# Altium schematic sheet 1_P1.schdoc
size 431 x 309 mm; Symbol: Sheet-Symbol_A1; Device: Sheet-Symbol_A1; Company: MadNick93; Drawed: Niccolo&apos; Ferrari; Reviewed: Niccolo&apos; Ferrari; Version: V4.0; Page Size: A1; @Project Name: Compact_LED_Driver_PWM_Single_ATtiny1616_Double; @Page Count: 1; @Update Date: 2024-02-11; @Create Date: 2024-02-08; @Schematic Name: schematic1; Part Number: NF-0001; @Page No: 1; @Page Name: P1; @Board Name: Board1; @Create Time: 16:56:16; @Update Time: 14:38:09
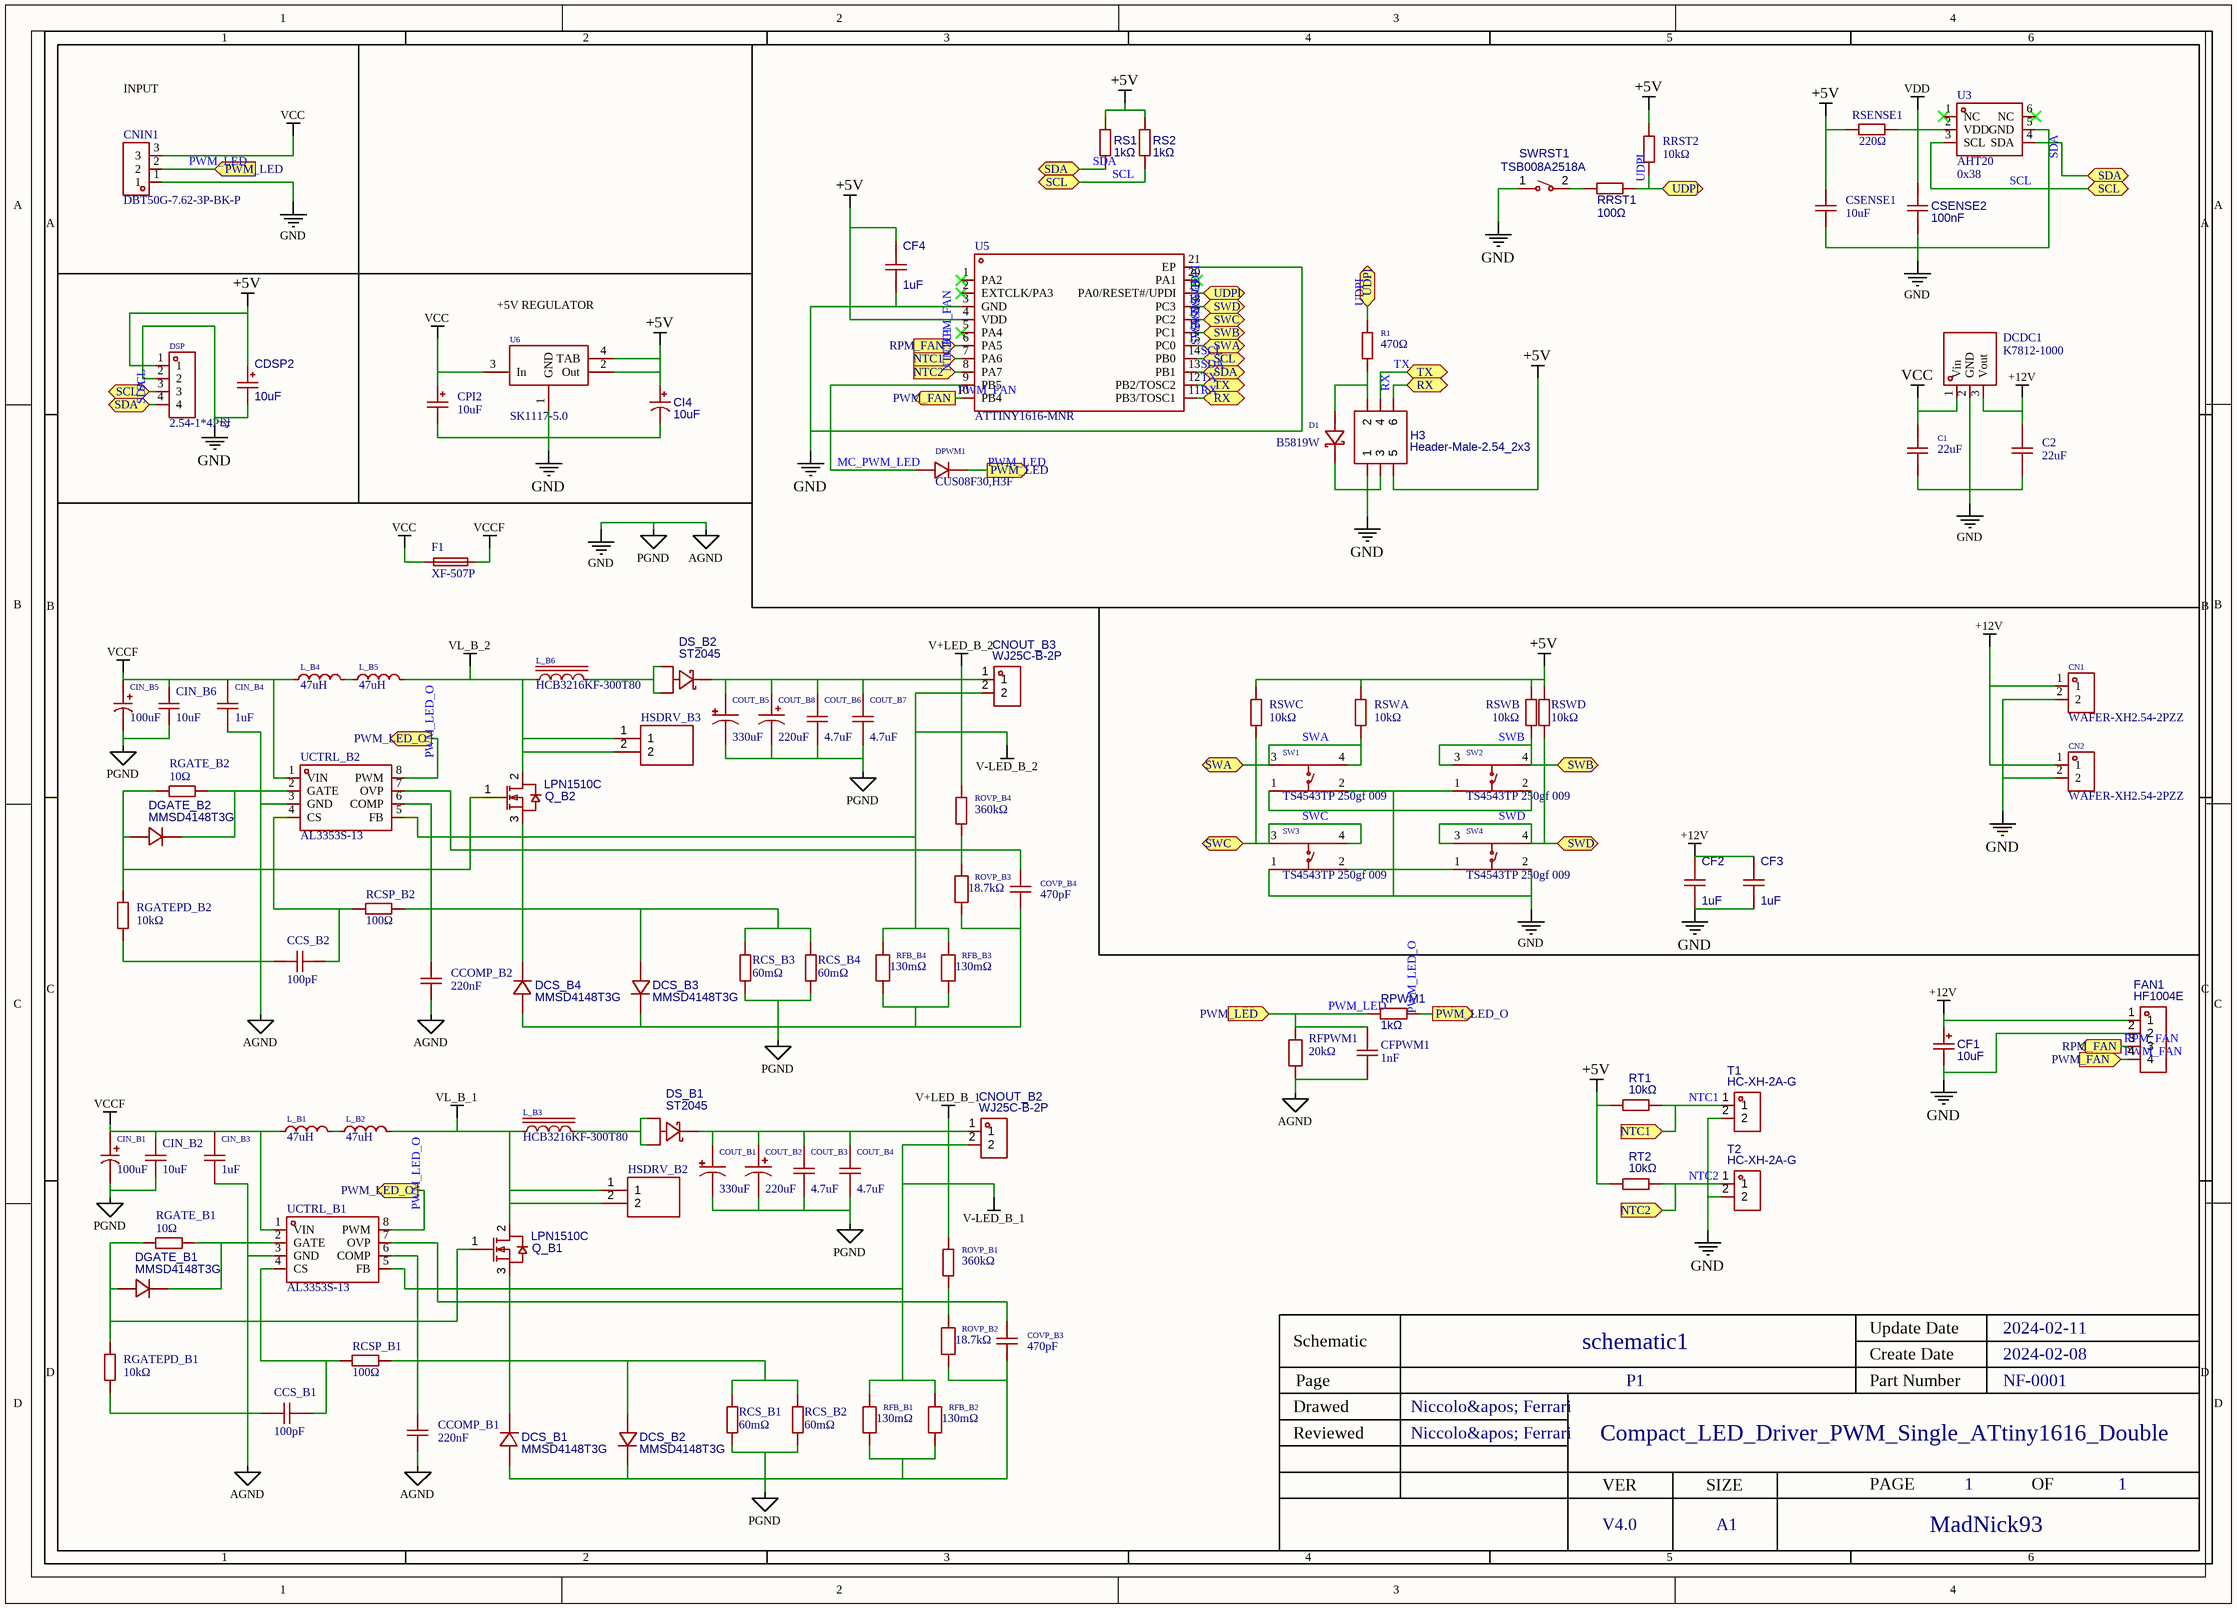
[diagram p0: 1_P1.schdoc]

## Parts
C1  22uF  [C0805]  (value not drawn)
C2  22uF  [C0805]  (value not drawn)
CCOMP_B1  220nF  [C0402]  (value not drawn)
CCOMP_B2  220nF  [C0402]  (value not drawn)
CCS_B1  100pF  [C0402]  (value not drawn)
CCS_B2  100pF  [C0402]  (value not drawn)
CDSP2  10uF  [CAP-SMD_L3.2-W1.6-R-RD]  (value not drawn)
CF1  10uF  [CAP-SMD_L3.5-W2.8]  (value not drawn)
CF2  1uF  [0402]  (value not drawn)
CF3  1uF  [0402]  (value not drawn)
CF4  1uF  [0402]  (value not drawn)
CFPWM1  1nF  [C0603]  (value not drawn)
CI4  10uF  [CAP-SMD_L3.2-W1.6]  (value not drawn)
CIN_B1  100uF  [CAP-TH_BD10.0-P5.00-D0.6-FD-A]  (value not drawn)
CIN_B2  10uF  [C0805]  (value not drawn)
CIN_B3  1uF  [C0402]  (value not drawn)
CIN_B4  1uF  [C0402]  (value not drawn)
CIN_B5  100uF  [CAP-TH_BD10.0-P5.00-D0.6-FD-A]  (value not drawn)
CIN_B6  10uF  [C0805]  (value not drawn)
CN1  WAFER-XH2.54-2PZZ  [CONN-TH_XH2.54-2P]  (value not drawn)
CN2  WAFER-XH2.54-2PZZ  [CONN-TH_XH2.54-2P]  (value not drawn)
CNIN1  DBT50G-7.62-3P-BK-P  [CONN-TH_3P-P7.62_L15.2-W24.4-EX4.2]  (value not drawn)
CNOUT_B2  WJ25C-B-2P  [CONN-TH_2P-P7.62_WJ25C-B-7.62-2P]  (value not drawn)
CNOUT_B3  WJ25C-B-2P  [CONN-TH_2P-P7.62_WJ25C-B-7.62-2P]  (value not drawn)
COUT_B1  330uF  [CAP-TH_BD10.0-P5.00-D1.0-FD]  (value not drawn)
COUT_B2  220uF  [CAP-TH_BD10.0-P5.00-D0.6-FD-A]  (value not drawn)
COUT_B3  4.7uF  [C1210]  (value not drawn)
COUT_B4  4.7uF  [C1210]  (value not drawn)
COUT_B5  330uF  [CAP-TH_BD10.0-P5.00-D1.0-FD]  (value not drawn)
COUT_B6  4.7uF  [C1210]  (value not drawn)
COUT_B7  4.7uF  [C1210]  (value not drawn)
COUT_B8  220uF  [CAP-TH_BD10.0-P5.00-D0.6-FD-A]  (value not drawn)
COVP_B3  470pF  [C0402]  (value not drawn)
COVP_B4  470pF  [C0402]  (value not drawn)
CPI2  10uF  [CASE-C_6032]  (value not drawn)
CSENSE1  10uF  [C0402]  (value not drawn)
CSENSE2  100nF  [C0402]  (value not drawn)
D1  B5819W  [SOD-123F_L2.7-W1.6-LS3.8-RD-1]  (value not drawn)
DCDC1  K7812-1000  [PWRM-TH_K78XX-1000]  (value not drawn)
DCS_B1  MMSD4148T3G  [SOD-123FL_L2.6-W1.6-LS3.4-RD]  (value not drawn)
DCS_B2  MMSD4148T3G  [SOD-123FL_L2.6-W1.6-LS3.4-RD]  (value not drawn)
DCS_B3  MMSD4148T3G  [SOD-123FL_L2.6-W1.6-LS3.4-RD]  (value not drawn)
DCS_B4  MMSD4148T3G  [SOD-123FL_L2.6-W1.6-LS3.4-RD]  (value not drawn)
DGATE_B1  MMSD4148T3G  [SOD-123FL_L2.6-W1.6-LS3.4-RD]  (value not drawn)
DGATE_B2  MMSD4148T3G  [SOD-123FL_L2.6-W1.6-LS3.4-RD]  (value not drawn)
DPWM1  CUS08F30,H3F  [SOD-323F_L2.0-W1.6-LS2.5-RD]  (value not drawn)
DS_B1  ST2045  [TO-277_3P-L5.4-W4.0-LS6.5-BR]  (value not drawn)
DS_B2  ST2045  [TO-277_3P-L5.4-W4.0-LS6.5-BR]  (value not drawn)
DSP  2.54-1*4P母  [HDR-TH_4P-P2.54-V-F]  (value not drawn)
F1  XF-507P  [CONN-TH_XF-507P]  (value not drawn)
FAN1  HF1004E  [CONN-TH_4P-P2.54_HF1004E]  (value not drawn)
H3  Header-Male-2.54_2x3  [HDR-TH_6P-P2.54-V-M-R2-C3-S2.54-1]  (value not drawn)
HSDRV_B2  XSD366-094  [xsd366094]  (value not drawn)
HSDRV_B3  XSD366-094  [xsd366094]  (value not drawn)
L_B1  47uH  [IND-TH_L17.8-W17.8-P13.00-D0.6]  (value not drawn)
L_B2  47uH  [IND-TH_L17.8-W17.8-P13.00-D0.6]  (value not drawn)
L_B3  HCB3216KF-300T80  [L1206]  (value not drawn)
L_B4  47uH  [IND-TH_L17.8-W17.8-P13.00-D0.6]  (value not drawn)
L_B5  47uH  [IND-TH_L17.8-W17.8-P13.00-D0.6]  (value not drawn)
L_B6  HCB3216KF-300T80  [L1206]  (value not drawn)
Q_B1  LPN1510C  [TO-220-3_L10.0-W4.5-P2.54-L]  (value not drawn)
Q_B2  LPN1510C  [TO-220-3_L10.0-W4.5-P2.54-L]  (value not drawn)
R1  470Ω  [R0402]  (value not drawn)
RCS_B1  60mΩ  [R2512]  (value not drawn)
RCS_B2  60mΩ  [R2512]  (value not drawn)
RCS_B3  60mΩ  [R2512]  (value not drawn)
RCS_B4  60mΩ  [R2512]  (value not drawn)
RCSP_B1  100Ω  [R0402]  (value not drawn)
RCSP_B2  100Ω  [R0402]  (value not drawn)
RFB_B1  130mΩ  [RES-SMD_L6.4-W3.2-R2512]  (value not drawn)
RFB_B2  130mΩ  [RES-SMD_L6.4-W3.2-R2512]  (value not drawn)
RFB_B3  130mΩ  [RES-SMD_L6.4-W3.2-R2512]  (value not drawn)
RFB_B4  130mΩ  [RES-SMD_L6.4-W3.2-R2512]  (value not drawn)
RFPWM1  20kΩ  [R0402]  (value not drawn)
RGATE_B1  10Ω  [R0402]  (value not drawn)
RGATE_B2  10Ω  [R0402]  (value not drawn)
RGATEPD_B1  10kΩ  [R0402]  (value not drawn)
RGATEPD_B2  10kΩ  [R0402]  (value not drawn)
ROVP_B1  360kΩ  [R0402]  (value not drawn)
ROVP_B2  18.7kΩ  [R0402]  (value not drawn)
ROVP_B3  18.7kΩ  [R0402]  (value not drawn)
ROVP_B4  360kΩ  [R0402]  (value not drawn)
RPWM1  1kΩ  [R0402]  (value not drawn)
RRST1  100Ω  [R0402]  (value not drawn)
RRST2  10kΩ  [R0402]  (value not drawn)
RS1  1kΩ  [R0402]  (value not drawn)
RS2  1kΩ  [R0402]  (value not drawn)
RSENSE1  220Ω  [R0402]  (value not drawn)
RSWA  10kΩ  [R0402]  (value not drawn)
RSWB  10kΩ  [R0402]  (value not drawn)
RSWC  10kΩ  [R0402]  (value not drawn)
RSWD  10kΩ  [R0402]  (value not drawn)
RT1  10kΩ  [R0402]  (value not drawn)
RT2  10kΩ  [R0402]  (value not drawn)
SW1  TS4543TP 250gf 009  [SW-SMD_4P-L4.5-W4.5-P3.00-LS6.9]  (value not drawn)
SW2  TS4543TP 250gf 009  [SW-SMD_4P-L4.5-W4.5-P3.00-LS6.9]  (value not drawn)
SW3  TS4543TP 250gf 009  [SW-SMD_4P-L4.5-W4.5-P3.00-LS6.9]  (value not drawn)
SW4  TS4543TP 250gf 009  [SW-SMD_4P-L4.5-W4.5-P3.00-LS6.9]  (value not drawn)
SWRST1  TSB008A2518A  [SW-SMD_L6.0-W3.5-LS8.2]  (value not drawn)
T1  HC-XH-2A-G  [CONN-TH_2P-P2.50_HC-XH-2A-G]  (value not drawn)
T2  HC-XH-2A-G  [CONN-TH_2P-P2.50_HC-XH-2A-G]  (value not drawn)
U3  I2C Address: 0x38  [SENSOR-SMD_L3.0-W3.0-P1.00-BR]  (hidden comment: AHT20)
U5  ATTINY1616-MNR  [QFN-20_L3.0-W3.0-P0.40-BL-EP1.7]  (value not drawn)
U6  SK1117-5.0  [SOT-223_L6.5-W3.5-P2.30-LS7.0-BR]  (value not drawn)
UCTRL_B1  AL3353S-13  [SOIC-8_L4.9-W3.9-P1.27-LS6.0-BL]  (value not drawn)
UCTRL_B2  AL3353S-13  [SOIC-8_L4.9-W3.9-P1.27-LS6.0-BL]  (value not drawn)

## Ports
NTC1 (in), NTC2 (in), PWM_FAN (in), PWM_FAN (out), PWM_LED (in), PWM_LED (out), PWM_LED_O (out), RPM_FAN (in), RPM_FAN (out), RX (bidir), SCL (bidir), SDA (bidir), SWA (bidir), SWB (bidir), SWC (bidir), SWD (bidir), TX (bidir), UDPI (bidir)

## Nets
+5V: CDSP2.1 CF4.1 CI4.1 CSENSE1.2 DSP.1 H3.5 RRST2.2 RS1.2 RS2.2 RSENSE1.1 RSWA.2 RSWB.2 RSWC.2 RSWD.2 RT1.1 RT2.1 U5.4(VDD) U6.2(Out) U6.4(TAB)
+12V: C2.1 CF1.1 CF2.1 CF3.1 CN1.1 CN2.1 DCDC1.3(Vout) FAN1.1
AGND: C1.2 C2.2 CCOMP_B1.2 CCOMP_B2.2 CCS_B1.2 CCS_B2.2 CDSP2.2 CF1.2 CF2.2 CF3.2 CF4.2 CFPWM1.1 CI4.2 CIN_B1.2 CIN_B2.2 CIN_B3.1 CIN_B4.1 CIN_B5.2 CIN_B6.2 CN1.2 CN2.2 CNIN1.1 COUT_B1.2 COUT_B2.2 COUT_B3.1 COUT_B4.1 COUT_B5.2 COUT_B6.1 COUT_B7.1 COUT_B8.2 COVP_B3.1 COVP_B4.1 CPI2.2 CSENSE1.1 CSENSE2.1 DCDC1.2(GND) DCS_B1.2(A) DCS_B2.1(C) DCS_B3.1(C) DCS_B4.2(A) DSP.2 FAN1.2 H3.1 RCS_B1.1 RCS_B2.1 RCS_B3.1 RCS_B4.1 RFB_B1.1 RFB_B2.1 RFB_B3.1 RFB_B4.1 RFPWM1.1 RGATEPD_B1.1 RGATEPD_B2.1 ROVP_B2.1 ROVP_B3.1 SW1.1(A) SW1.2(B) SW2.1(A) SW2.2(B) SW3.1(A) SW3.2(B) SW4.1(A) SW4.2(B) SWRST1.1 T1.2 T2.2 U3.5(GND) U5.3(GND) U5.21(EP) U6.1(GND) UCTRL_B1.3(GND) UCTRL_B2.3(GND)  [also labelled GND, PGND]
V+LED_B_1: CNOUT_B2.1 COUT_B1.1 COUT_B2.1 COUT_B3.2 COUT_B4.2 DS_B1.2(K) ROVP_B1.2
V+LED_B_2: CNOUT_B3.1 COUT_B5.1 COUT_B6.2 COUT_B7.2 COUT_B8.1 DS_B2.2(K) ROVP_B4.2
V-LED_B_1: CNOUT_B2.2 RFB_B1.2 RFB_B2.2 UCTRL_B1.5(FB)
V-LED_B_2: CNOUT_B3.2 RFB_B3.2 RFB_B4.2 UCTRL_B2.5(FB)
VCC: C1.1 CNIN1.3 CPI2.1 DCDC1.1(Vin) F1.1 F1.2 U6.3(In)
VCCF: CIN_B1.1 CIN_B2.1 CIN_B3.2 CIN_B4.2 CIN_B5.1 CIN_B6.1 F1.3 F1.4 L_B1.1 L_B4.1 UCTRL_B1.1(VIN) UCTRL_B2.1(VIN)
VDD: CSENSE2.2 RSENSE1.2 U3.2(VDD)
VL_B_1: HSDRV_B2.1 HSDRV_B2.2 L_B2.2 L_B3.1 Q_B1.2(D)
VL_B_2: HSDRV_B3.1 HSDRV_B3.2 L_B5.2 L_B6.1 Q_B2.2(D)
MC_PWM_LED: DPWM1.2(A) U5.9(PB5)
NTC1: RT1.2 T1.1 U5.7(PA6) ; port NTC1
NTC2: RT2.2 T2.1 U5.8(PA7) ; port NTC2
PWM_FAN: FAN1.4 U5.10(PB4) ; port PWM_FAN
PWM_LED: CFPWM1.2 CNIN1.2 DPWM1.1(C) RFPWM1.2 RPWM1.2 ; port PWM_LED
PWM_LED_O: RPWM1.1 UCTRL_B1.8(PWM) UCTRL_B2.8(PWM) ; port PWM_LED_O
RPM_FAN: FAN1.3 U5.6(PA5) ; port RPM_FAN
RX: H3.6 U5.11(PB3/TOSC1) ; port RX
SCL: DSP.3 RS2.1 U3.3(SCL) U5.14(PB0) ; port SCL
SDA: DSP.4 RS1.1 U3.4(SDA) U5.13(PB1) ; port SDA
SWA: RSWA.1 SW1.3(C) SW1.4(D) U5.15(PC0) ; port SWA
SWB: RSWB.1 SW2.3(C) SW2.4(D) U5.16(PC1) ; port SWB
SWC: RSWC.1 SW3.3(C) SW3.4(D) U5.17(PC2) ; port SWC
SWD: RSWD.1 SW4.3(C) SW4.4(D) U5.18(PC3) ; port SWD
TX: H3.4 U5.12(PB2/TOSC2) ; port TX
UDPI: R1.2 RRST1.1 RRST2.1 U5.19(PA0/RESET#/UPDI) ; port UDPI
NetCCOMP_B1_1: CCOMP_B1.1 UCTRL_B1.6(COMP)
NetCCOMP_B2_1: CCOMP_B2.1 UCTRL_B2.6(COMP)
NetCCS_B1_1: CCS_B1.1 RCSP_B1.1 UCTRL_B1.4(CS)
NetCCS_B2_1: CCS_B2.1 RCSP_B2.1 UCTRL_B2.4(CS)
NetCOVP_B3_2: COVP_B3.2 ROVP_B1.1 ROVP_B2.2 UCTRL_B1.7(OVP)
NetCOVP_B4_2: COVP_B4.2 ROVP_B3.2 ROVP_B4.1 UCTRL_B2.7(OVP)
NetD1_1: D1.1(K) H3.3
NetD1_2: D1.2(A) H3.2 R1.1
NetDCS_B1_1: DCS_B1.1(C) DCS_B2.2(A) Q_B1.3(S) RCS_B1.2 RCS_B2.2 RCSP_B1.2
NetDCS_B3_2: DCS_B3.2(A) DCS_B4.1(C) Q_B2.3(S) RCS_B3.2 RCS_B4.2 RCSP_B2.2
NetDGATE_B1_1: DGATE_B1.1(C) RGATE_B1.2 UCTRL_B1.2(GATE)
NetDGATE_B1_2: DGATE_B1.2(A) Q_B1.1(G) RGATE_B1.1 RGATEPD_B1.2
NetDGATE_B2_1: DGATE_B2.1(C) RGATE_B2.2 UCTRL_B2.2(GATE)
NetDGATE_B2_2: DGATE_B2.2(A) Q_B2.1(G) RGATE_B2.1 RGATEPD_B2.2
NetDS_B1_1: DS_B1.1(A) DS_B1.3(A) L_B3.2
NetDS_B2_1: DS_B2.1(A) DS_B2.3(A) L_B6.2
NetL_B1_2: L_B1.2 L_B2.1
NetL_B4_2: L_B4.2 L_B5.1
NetRRST1_2: RRST1.2 SWRST1.2

Not connected (* = marked no-connect by the designer): U3 1(NC)* 6(NC)*; U5 1(PA2)* 2(EXTCLK/PA3)* 5(PA4)* 20(PA1)*

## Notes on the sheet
- INPUT
- (near U6) +5V REGULATOR

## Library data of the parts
C1 = CGA0805X5R226M350MT: Capacitance:22uF Tolerance:±20% Tolerance:±20% Voltage Rated: Temperature Coefficient:; Manufacturer: HRE(芯声); Add into BOM: yes; Tolerance: ±20%
C2 = CL21A226MAYNNNE: Capacitance: Tolerance:±20% Tolerance:±20% Voltage Rated: Temperature Coefficient:; Manufacturer: SAMSUNG(三星); Add into BOM: yes; Tolerance: ±20%
CCOMP_B1 CCOMP_B2 = CL05A224KA5NNNC: Capacitance: Tolerance:±10% Tolerance:±10% Voltage Rated: Temperature Coefficient:; Manufacturer: SAMSUNG(三星); Add into BOM: yes; Tolerance: ±10%
CCS_B1 CCS_B2 = TCC0402COG101K500AT: Capacitance: Tolerance:±10% Tolerance:±10% Voltage Rated: Temperature Coefficient:; Manufacturer: CCTC(三环); Add into BOM: yes; Tolerance: ±10%
CDSP2 = 10uF: Manufacturer: AVX; Manufacturer Part: TAJA106K010RNJ; Convert to PCB: yes
CF1 = 10uF: Manufacturer: Xiangyee; Manufacturer Part: CA45-B025K106T; Convert to PCB: yes
CF2-CF4 = 1uF: Manufacturer: SAMSUNG; Manufacturer Part: CL05A105KA5NQNC; Convert to PCB: yes
CFPWM1 = FN18X102K500PSG: Capacitance: Tolerance:±10% Tolerance:±10% Voltage Rated: Temperature Coefficient:; Manufacturer: PSA(信昌电陶); Add into BOM: yes; Tolerance: ±10%
CI4 = 10uF: Manufacturer: Xiangyee; Manufacturer Part: CA45-A016K106T; Convert to PCB: yes
CIN_B1 CIN_B5 = 1010631012R00: Capacitance: Tolerance:±20% Tolerance:±20% Rated Voltage: φD: L: Operating Temperature:-55℃~+105℃ Operating Temperature:-55℃~+105℃; Manufacturer: NJCON(永立); Add into BOM: yes; Tolerance: ±20%
CIN_B2 CIN_B6 = CL21A106KAYNNNE_C15850: Capacitance: Tolerance:±10% Tolerance:±10% Voltage Rated: Temperature Coefficient:; Manufacturer: SAMSUNG(三星); Add into BOM: yes; Tolerance: ±10%
CIN_B3 CIN_B4 = CL05A105KA5NQNC: Capacitance: Tolerance:±10% Tolerance:±10% Voltage Rated: Temperature Coefficient:; Manufacturer: SAMSUNG(三星); Add into BOM: yes; Tolerance: ±10%
CN1 CN2 = WAFER-XH2.54-2PZZ: Pins Structure:1x2P Pitch:2.54mm Mounting Style:Straight Number of Pins:2P Number of Rows:1 Number of PINs Per Row:2 Current Rating (Max):2A Operating Temperature Range:-25℃~+85℃ Operating Temperature Range:-25℃~+85℃; Manufacturer: XUNPU(讯普); Add into BOM: yes; Pins Structure: 1x2P; Pitch: 2.54mm; Number of PINs Per Row: 2; Current Rating (Max): 2A
CNIN1 = DBT50G-7.62-3P-BK-P: Barrier Type:带盖板 Pitch:7.62mm Number of PINs Per Row:3 Number of Rows:1 Mounting Style:直针 Pin Location:边脚 Current Rating (Max):20A Voltage Rating (Max):300V Wire Gauge - AWG:12~22 Wire Gauge - mm?:- Operating Temperature Range:-40℃~+105℃ Operating Tempera; Manufacturer: DIBO(地博电气); Add into BOM: yes; Barrier Type: 带盖板; Pitch: 7.62mm; Number of PINs Per Row: 3; Pin Location: 边脚; Current Rating (Max): 20A; Voltage Rating (Max): 300V; Wire Gauge - AWG: 12~22
CNOUT_B2 CNOUT_B3 = WJ25C-B-2P: Manufacturer: KANGNEX(康奈克斯电气); Manufacturer Part: WJ25C-B-7.62-2P; Convert to PCB: yes
COUT_B1 COUT_B5 = RG063M331LO10*20TA-1A1E: Capacitance: Tolerance:±20% Tolerance:±20% Rated Voltage: Lead Spacing: φD: L: Lifetime @ Temp:7000hrs@105℃; Manufacturer: BERYL(绿宝石); Add into BOM: yes; Tolerance: ±20%
COUT_B2 COUT_B8 = SPZ1JM221G15O00RAXXX: Capacitance: Tolerance:±20% Tolerance:±20% Rated Voltage: Ripple Current:2.65A@100kHz Equivalent Series Resistance(ESR):20mΩ@100kHz Type:Polymer Lead Spacing: φD: L: Lifetime @ Temp:2000hrs@105℃ Operating Temperature:-55℃~+105℃ Operating Temperature:-55℃~; Manufacturer: AISHI(艾华集团); Add into BOM: yes; Tolerance: ±20%
COUT_B3 COUT_B4 COUT_B6 COUT_B7 = FS32X475K101EGG: Capacitance: Tolerance:±10% Tolerance:±10% Voltage Rated: Temperature Coefficient:; Manufacturer: PSA(信昌电陶); Add into BOM: yes; Tolerance: ±10%
COVP_B3 COVP_B4 = 0402B471K500NT: Capacitance: Tolerance:±10% Tolerance:±10% Voltage Rated: Temperature Coefficient:; Manufacturer: FH(风华); Add into BOM: yes; Tolerance: ±10%
CPI2 = TAJC106K035RNJ: Capacitance: Tolerance:±10% Tolerance:±10% Rated Voltage: Equivalent Series Resistance(ESR):1.6Ω@100kHz Operating Temperature:-55℃~+125℃ Operating Temperature:-55℃~+125℃; Manufacturer: Kyocera AVX; Add into BOM: yes; Tolerance: ±10%
CSENSE1 = CL05A106MQ5NUNC: Capacitance: Tolerance:±20% Tolerance:±20% Voltage Rated: Temperature Coefficient:; Manufacturer: SAMSUNG(三星); Add into BOM: yes; Tolerance: ±20%
CSENSE2 = 100nF: Manufacturer: CCTC(三环); Manufacturer Part: TCC0402X7R104K160AT; Convert to PCB: yes
D1 = B5819W_C2943878: Diode Configuration:- Forward Voltage (Vf@If):580mV@1A Reverse Voltage (Vr):40V Average Rectified Current (Io):1A Reverse Leakage Current (Ir):50uA@40V; Manufacturer: GOODWORK(固得沃克); Add into BOM: yes; Reverse Voltage (Vr): 40V; Average Rectified Current (Io): 1A
DCDC1 = K7812-1000_C5199013: Conversion Type:DC-DC Input Voltage(DC):16V~30V Input Voltage(DC):16V~30V Output Voltage:12V；-12V Output Voltage:12V；-12V Output Power:12W Output Current (Max):1A Output Current (Max):1A Function:降压型 Conversion Efficiency:93% Conversion Efficiency:93% Max; Manufacturer: JETEKPS(健特); Add into BOM: yes; Conversion Type: DC-DC; Output Power: 12W; Output Current (Max): 1A; Function: 降压型; Conversion Efficiency: 93%; Maximum Capacitive Load: 680uF
DCS_B1-DCS_B4 DGATE_B1 DGATE_B2 = MMSD4148T3G: Manufacturer: ONSemicon; Convert to PCB: yes
DPWM1 = CUS08F30,H3F: Forward Voltage (Vf@If):220mV@10mA Reverse Voltage (Vr):30V Average Rectified Current (Io):800mA Reverse Leakage Current (Ir):50uA@30V; Manufacturer: TOSHIBA(东芝); Add into BOM: yes; Reverse Voltage (Vr): 30V; Average Rectified Current (Io): 800mA
DS_B1 DS_B2 = ST2045: Manufacturer: MDD（MicrodiodeElectronics）; Convert to PCB: yes
DSP = 2.54-1*4P母: Number of Rows:Plugin Number of Holes:4P Pitch:2.54mm Holes Structure:1x4P Row Spacing:- Mounting Type:Straight Circular Hole / Square Hole:Square Holes Current Rating (Max):3A Voltage Rating (Max):- Holes Direction:Top Insulation Height:- Contact Materia; Manufacturer: BOOMELE(博穆精密); Add into BOM: yes; Number of Holes: 4P; Pitch: 2.54mm; Holes Structure: 1x4P; Current Rating (Max): 3A; Holes Direction: Top
F1 = XF-507P: Fuseholder Type:- Fuse Type:- Fuse Size:-; Manufacturer: XFCN(兴飞); Add into BOM: yes
FAN1 = HF1004E: Manufacturer: FOXCONN(富士康); Convert to PCB: yes
H3 = Header-Male-2.54_2x3: Manufacturer: BOOMELE; Convert to PCB: yes; Origin Footprint: HDR-TH_6P-P2.54-V-R2-C3-S2.54
HSDRV_B2 HSDRV_B3 = XSD366-094: Part Number: C286227; Manufacturer: XSD; Add into BOM: yes
L_B1 L_B2 L_B4 L_B5 = PDPMAA1712-470MP: Inductance: Tolerance:±20% Tolerance:±20% Rated Current: Type:- DC Resistance (DCR): Saturation Current (Isat):14A Ratings:AEC-Q200; Manufacturer: PROD(谱罗德); Add into BOM: yes; Tolerance: ±20%; Saturation Current (Isat): 14A
L_B3 L_B6 = HCB3216KF-300T80: Impedance @ Frequency:30Ω@100MHz Tolerance:±25% Tolerance:±25% DC Resistance:10mΩ Current Rating:8A Circuits:1; Manufacturer: TAI-TECH(台庆); Add into BOM: yes; Tolerance: ±25%; DC Resistance: 10mΩ; Current Rating: 8A; Circuits: 1
Q_B1 Q_B2 = LPN1510C: Manufacturer: Infineon Technologies; Manufacturer Part: IRFB4110PBF; Convert to PCB: yes
R1 = 0402WGJ0471TCE: Type:Thick Film Resistors Resistance: Tolerance:±5% Tolerance:±5% Power(Watts): Overload Voltage (Max): Temperature Coefficient:±100ppm/℃ Temperature Coefficient:±100ppm/℃ Operating Temperature Range:-55℃~+155℃ Operating Temperature Range:-55℃~+155℃; Manufacturer: UNI-ROYAL(厚声); Add into BOM: yes; Tolerance: ±5%
RCS_B1-RCS_B4 = MA251230FR060FZ: Type:Current Sensing Resistors Resistance: Tolerance:±1% Tolerance:±1% Power(Watts): Temperature Coefficient:±50ppm/℃ Temperature Coefficient:±50ppm/℃; Manufacturer: EVER OHMS(天二科技); Add into BOM: yes; Tolerance: ±1%
RCSP_B1 RCSP_B2 = 0402WGJ0101TCE: Resistance: Tolerance:±5% Tolerance:±5% Power(Watts): Overload Voltage (Max): Temperature Coefficient:±100ppm/℃ Temperature Coefficient:±100ppm/℃ Type:Thick Film Resistors Operating Temperature Range:-55℃~+155℃ Operating Temperature Range:-55℃~+155℃; Manufacturer: UNI-ROYAL(厚声); Add into BOM: yes; Tolerance: ±5%
RFB_B1-RFB_B4 = HoLR2512-130mR-1%: Type:Current Sensing Resistors Resistance:130mΩ Tolerance:±1% Tolerance:±1% Power(Watts): Temperature Coefficient:±50ppm/℃ Temperature Coefficient:±50ppm/℃ Mounting Sytle:Surface Mount; Manufacturer: Milliohm(毫欧); Add into BOM: yes; Tolerance: ±1%
RFPWM1 = SCR0402J20K: Resistance: Tolerance:±5% Tolerance:±5%; Manufacturer: VO(翔胜); Add into BOM: yes; Tolerance: ±5%
RGATE_B1 RGATE_B2 = 0402WGJ0100TCE: Resistance: Tolerance:±5% Tolerance:±5% Power(Watts): Overload Voltage (Max): Temperature Coefficient:±400ppm/℃ Temperature Coefficient:±400ppm/℃ Type:Thick Film Resistors Operating Temperature Range:-55℃~+155℃ Operating Temperature Range:-55℃~+155℃; Manufacturer: UNI-ROYAL(厚声); Add into BOM: yes; Tolerance: ±5%
RGATEPD_B1 RGATEPD_B2 RRST2 RSWA RSWB RSWC RSWD = RTT021002FTH: Type:Thick Film Resistors Resistance: Tolerance:±1% Tolerance:±1% Power(Watts): Temperature Coefficient:±100ppm/℃ Temperature Coefficient:±100ppm/℃ Overload Voltage (Max): Operating Temperature Range:-55℃~+155℃ Operating Temperature Range:-55℃~+155℃; Manufacturer: RALEC(旺诠); Add into BOM: yes; Tolerance: ±1%
ROVP_B1 ROVP_B4 = 0402WGF3303TCE: Resistance:330000Ω Tolerance:±1% Tolerance:±1% Power(Watts): Overload Voltage (Max): Temperature Coefficient:±100ppm/℃ Temperature Coefficient:±100ppm/℃ Type:Thick Film Resistors Operating Temperature Range:-55℃~+155℃ Operating Temperature Range:-55℃~+155; Manufacturer: UNI-ROYAL(厚声); Manufacturer Part: 0402WGF3603TCE; Add into BOM: yes; Tolerance: ±1%
ROVP_B2 ROVP_B3 = SCR0402J13K: Resistance: Tolerance:±5% Tolerance:±5%; Manufacturer: UNI-ROYAL(Uniroyal Elec); Manufacturer Part: 0402WGF1872TCE; Add into BOM: yes; Tolerance: ±5%
RPWM1 RS1 RS2 = 1kΩ: Manufacturer: UNI-ROYAL(厚声); Manufacturer Part: 0402WGJ0102TCE; Convert to PCB: yes
RRST1 = 100Ω: Manufacturer: UNI-ROYAL(厚声); Manufacturer Part: 0402WGJ0101TCE; Convert to PCB: yes
RSENSE1 = 0402WGJ0221TCE: Resistance: Tolerance:±5% Tolerance:±5% Power(Watts): Overload Voltage (Max): Temperature Coefficient:±100ppm/℃ Temperature Coefficient:±100ppm/℃ Type:Thick Film Resistors Operating Temperature Range:-55℃~+155℃ Operating Temperature Range:-55℃~+155℃; Manufacturer: UNI-ROYAL(厚声); Add into BOM: yes; Tolerance: ±5%
RT1 RT2 = 10kΩ: Manufacturer: UNI-ROYAL(厚声); Manufacturer Part: 0402WGF1002TCE; Convert to PCB: yes
SW1-SW4 = TS4543TP 250gf 009: Circuit:SPST Actuator Style:Round Button Switch Length:4.5mm Switch Width:4.5mm Switch Height:4.3mm Strike Gundam:不带 Contact Current:50mA Voltage Rating (AC):- Voltage Rating (DC):12V Power Rating:- Mounting Style:Brick nogging Insulation Resistance:100MΩ; Manufacturer: SHOU HAN(首韩); Add into BOM: yes; Circuit: SPST; Switch Length: 4.5mm; Switch Height: 4.3mm; Strike Gundam: 不带; Contact Current: 50mA; Voltage Rating (DC): 12V; Insulation Resistance: 100MΩ; Actuator/Cap Color: Black; With Lamp: No; Mechanical Life: 100000次
SWRST1 = TSB008A2518A: Manufacturer: BZCN(博众电气); Convert to PCB: yes
T1 T2 = HC-XH-2A-G: Manufacturer: HCTL(华灿天禄); Convert to PCB: yes
U3 = AHT20: Manufacturer: 广州奥松; Symbol: AHT20_C2757850; Add into BOM: yes
U5 = ATTINY1616-MNR: CPU Core:AVR Program Storage Size:16KB RAM Size:2KB GPIO Ports Number:18 Operating Voltage Range:1.8V~5.5V Operating Voltage Range:1.8V~5.5V CPU Maximum Speed:20MHz Program Memory Type:FLASH Operating Temperature Range:-40℃~+105℃ Operating Temperature Ran; Manufacturer: MICROCHIP(美国微芯); Add into BOM: yes; CPU Core: AVR; Program Storage Size: 16KB; RAM Size: 2KB; GPIO Ports Number: 18; CPU Maximum Speed: 20MHz; Program Memory Type: FLASH; ADC (Bit): 10bit; DAC (Bit): 8bit; Peripheral/Function: WDT；PWM; Watchdog: 有
U6 = SK1117-5.0: Output Type:- Maximum Input Voltage:35V Output Voltage:5V Output Voltage:5V Output Current:1.4A Power Supply Rejection Ratio (PSRR):- Dropout Voltage:1.3V Quiescent Current (Ground Current):5mA Noise:- Feature:- Operating Temperature:-40℃~+85℃ Operating T; Manufacturer: SHIKUES(时科); Symbol: AMS1117-5.0_C165483; Add into BOM: yes; Maximum Input Voltage: 35V; Output Voltage: 5V; Output Current: 1.4A; Dropout Voltage: 1.3V; Quiescent Current (Ground Current): 5mA; Output Polarity: 正
UCTRL_B1 UCTRL_B2 = AL3353S-13: Manufacturer: DIODES(美台); Add into BOM: yes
